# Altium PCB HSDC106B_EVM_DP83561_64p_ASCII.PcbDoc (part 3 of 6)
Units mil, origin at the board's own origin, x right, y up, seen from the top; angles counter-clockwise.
Board outline 8750.24 x 6394.7 mil, 6 copper layers (Top Layer, GND, SIG1, SIG2, GND1, Bottom Layer), stack 60.4 mil thick; 475 components, 330 nets, 1628 pads, 1086 vias.
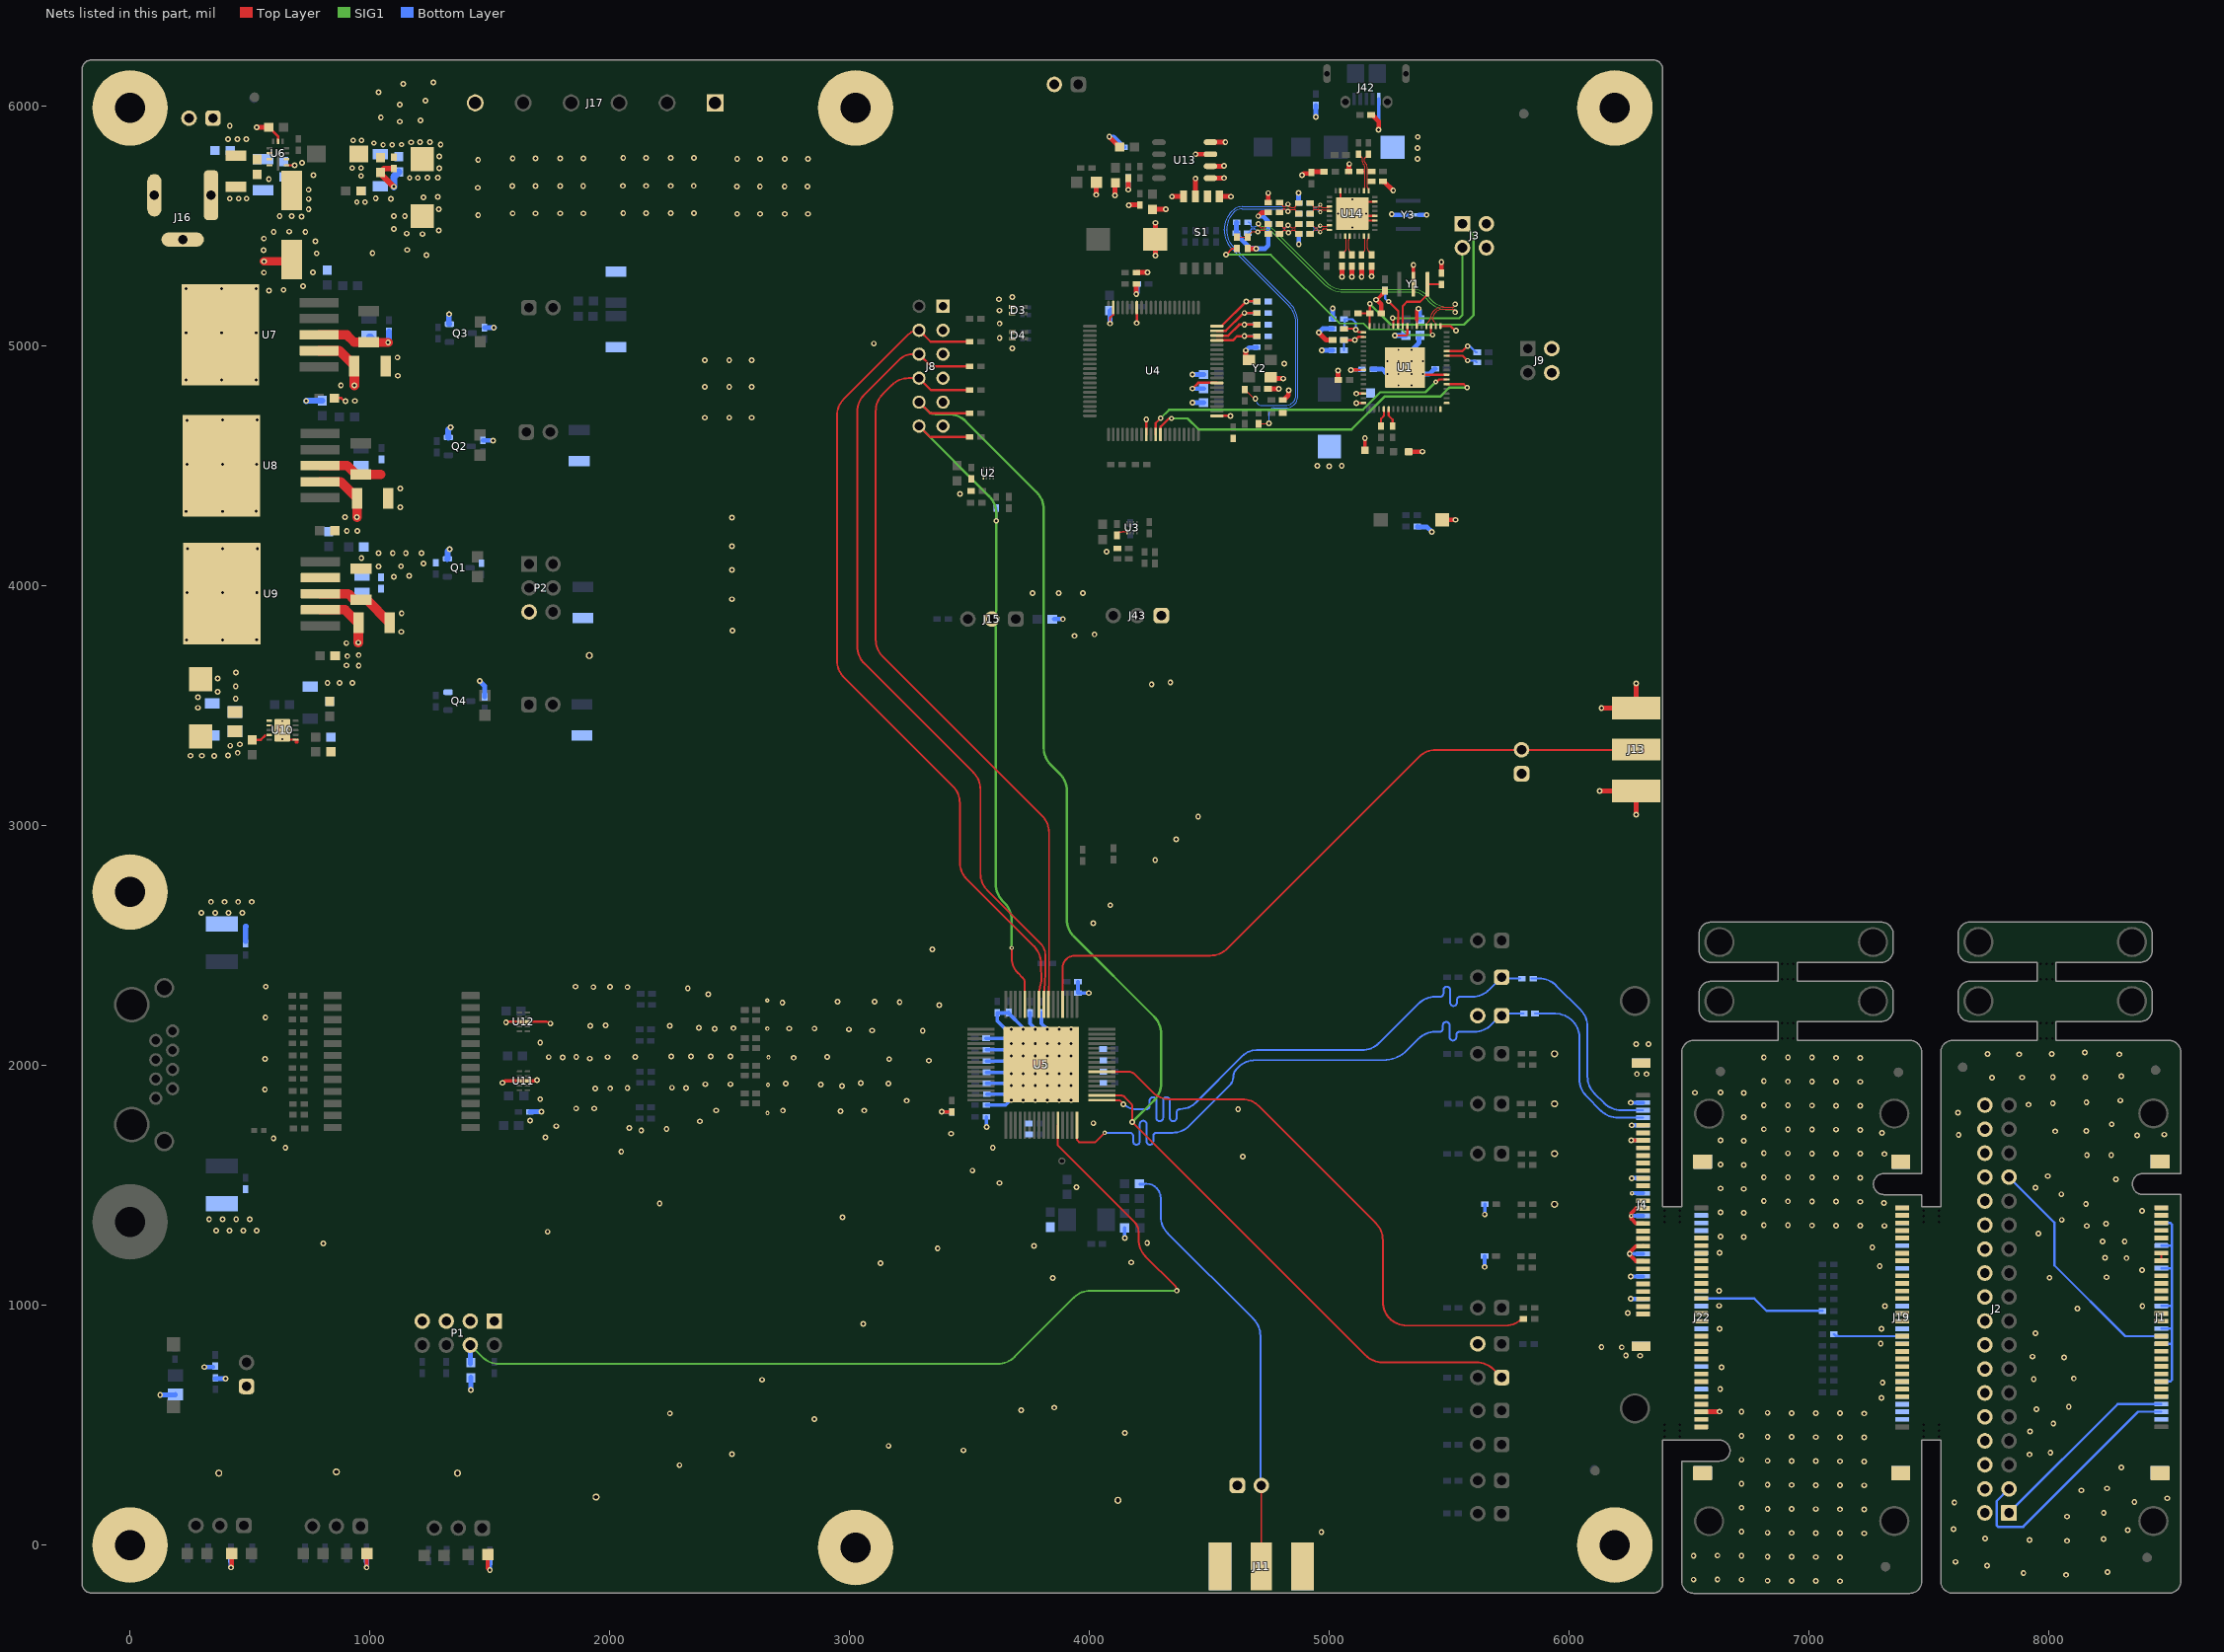
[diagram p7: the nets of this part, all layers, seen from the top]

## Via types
v1: diameter 24, hole 12, Top Layer to Bottom Layer, tented both sides, 905 vias
v2: diameter 24, hole 12, Top Layer to Bottom Layer, 63 vias
v3: diameter 18, hole 7.87, Top Layer to Bottom Layer, tented both sides, 53 vias
v4: diameter 22, hole 10, Top Layer to Bottom Layer, tented both sides, 43 vias
v5: diameter 19.68, hole 7.87, Top Layer to Bottom Layer, 21 vias
v6: diameter 22, hole 12, Top Layer to Bottom Layer, tented both sides, 1 vias

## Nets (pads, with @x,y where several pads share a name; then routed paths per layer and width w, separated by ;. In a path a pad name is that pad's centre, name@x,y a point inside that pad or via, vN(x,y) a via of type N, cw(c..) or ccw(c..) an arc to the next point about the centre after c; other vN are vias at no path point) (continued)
3V3: C80.1 C81.1 C83.1 P2.5 R100.2 R102.2 R103.2 R104.2 R105.2 R108.1 U9.4 | length 159.3
  Bottom Layer w20: v1(1458,3603.7) 1478.6,3583.1 R105.2@1478.6,3537.23 ; R103.2@1471.6,4607.23 1511.98,4607.23 v1@1513.6,4605.61 ; R104.2@1477.6,5077.23 v1@1519.22,5077.23
  other v1: 1099.81,4038.28 1163.01,4042.87 1036.21,4081.28 1129.81,4082.28 1223.01,4093.93 964.81,4116.28 1036,4136.7 1095,4136.7 1150,4136.7 1215,4136.7 1513.6,4606.61 1516.6,5077.61
5V: C50.1 C57.1 C58.2 C59.2 C60.1 C61.2 C68.1 C78.1 C85.1 C91.1 C92.2 C93.1 J17.1 J21.2 L1.2 R21.2 R22.2 R24.2 R26.2 R93.2 U7.2 U8.2 U9.2 U10.1 U10.2 U10.4 | length 925.2
  Top Layer w10: R26.2@508.6,3358.6 545.57,3358.6 562.66,3375.68 ; v1(897.6,4771.01) 893.54,4771.01 880.94,4783.61 ; R21.2@851.09,4783.61 880.94,4783.61 ; R21.2@851.09,4783.61 880.94,4783.61 ; R21.2@851.09,4783.61 880.94,4783.61
  Top Layer w40: U7.2@788.42,4980.77 872.93,4980.77 C50.1@933,4920.7 ; U8.2@792.42,4434.77 877.93,4434.77 C68.1@935,4377.7 ; U9.2@793.42,3900.77 896.93,3900.77 944,3853.7 C78.1@948,3853.7 ; v1(935.04,4836.74) C50.1@935.04,4917.7 ; v1(946.04,4286.74) C68.1@946.04,4365.7 ; v1(952.04,3763.74) C78.1@952.04,3846.7
  other v1: 350.6,3290.61 252,3292.1 299.6,3292.1 408.6,3292.61 448.42,3304.28 417.6,3333.61 457.6,3339.61 953,3667.7 902,3668.7 905.6,3707.61 953,3711.7 901.6,3761.61 903.6,4229.61 948,4229.7 896,4286.74 938,4771.7 878.97,4836.74 1239.44,5703.61 1283.6,5703.61 1289.6,5742.61 1289.6,5791.43 1294.64,5840.74 1172.13,5850.04 1209.6,5851.61 1250.6,5851.61
  other v4: 945.6,5600.61 979.6,5600.61 1165.6,5702.61 1200.21,5702.61 963.6,5709.62 925.76,5743.61 963.6,5743.61 1054.89,5839.61 1092.9,5839.61 1131.39,5840.74 1016.33,5847.02 930.06,5858.87 965.6,5858.61
5V-36V: C63.1 C64.1 C65.1 C66.1 C67.1 F1.1 U6.2 U6.9 U6.10
  other v1: 714.83,5540.45 623.6,5542.61 674.6,5542.61 744.6,5571.61 744.6,5613.61 744.6,5652.61 764.6,5712.61 716.75,5764.98 407.79,5863.96 447.23,5863.96 485.27,5863.96
5V-36V_jack: F1.2 J16.1 J18.1
AUTO_RECOVER: J8.10 J39.1 R45.1 U5.34 | length 5923.3
  Top Layer w8: U5.34@4051.41,1875.27 4130.94,1875.27 cw(c4130.94,1852.95) 4146.73,1868.74 4173.36,1842.1 cw(c4159.75,1828.49) 4179,1828.49 v1(4179,1763.7) 5151.24,791.46 ccw(c5221.96,862.17) 5221.96,762.17 5614.17,762.17 cw(c5614.17,662.17) 5684.88,732.88 J39.1@5718.99,698.77
  Top Layer w10: J8.10@3289.6,4766.61 3335.6,4720.61 R45.1@3500.98,4720.61
  SIG1 w10: J8.10@3289.6,4766.61 3326.16,4730.04 ccw(c3358.6,4762.48) 3358.6,4716.61 3412.67,4716.61 cw(c3412.67,4616.61) 3483.38,4687.32 3780.31,4390.39 cw(c3709.6,4319.68) 3809.6,4319.68 3809.6,3325.03 ccw(c3909.6,3325.03) 3838.89,3254.32 3876.31,3216.9 cw(c3805.6,3146.18) 3905.6,3146.18 3905.6,2609.03 ccw(c4005.6,2609.03) 3934.89,2538.32 4269.71,2203.49 cw(c4199,2132.78) 4299,2132.78 4299,1925.12 cw(c4199,1925.12) 4269.71,1854.41 v1(4179,1763.7)
BoardRev0: R49.1 R58.2 U4.77 | length 225.6
  Top Layer w10: U4.77@4531.24,5024.42 4598.31,5024.42 4615.69,5041.8 v1(4646.33,5041.8) R49.1@4697.98,5041.8
  Bottom Layer w10: v1(4646.33,5041.8) R58.2@4697.98,5041.8
BoardRev1: R50.1 R59.2 U4.78 | length 237.4
  Top Layer w10: U4.78@4531.24,5044.1 4578.62,5044.1 4624.59,5090.07 v1(4646.33,5090.07) R50.1@4697.98,5090.07
  Bottom Layer w10: v1(4646.33,5090.07) R59.2@4697.98,5090.07
BoardRev2: R52.1 R60.2 U4.79 | length 249.3
  Top Layer w10: U4.79@4531.24,5063.79 4567.78,5063.79 4639.65,5135.66 4643.65,5135.66 v1(4646.33,5138.34) R52.1@4697.98,5138.34
  Bottom Layer w10: v1(4646.33,5138.34) R60.2@4697.98,5138.34
BoardRev3: R53.1 R61.2 U4.80 | length 255.5
  Top Layer w10: U4.80@4531.24,5083.47 4553.38,5083.47 4554.22,5084.31 4554.22,5087.23 v1(4653.6,5186.61) R53.1@4697.98,5186.61
  Bottom Layer w10: v1(4653.6,5186.61) R61.2@4697.98,5186.61
CLKOUT: J13.1 J14.2 U5.52 | length 2920.1
  Top Layer w8: U5.52@3888.14,2255.08 3888.14,2407.15 cw(c3939.6,2407.15) 3939.6,2458.61 4504.18,2458.61 ccw(c4504.18,2558.61) 4574.89,2487.9 5374.44,3287.45 cw(c5445.15,3216.74) 5445.15,3316.74 J14.2@5801.67,3316.74 6276.29,3316.74 ccw(c6276.29,3321.41) J13.1@6279.6,3318.11
COL: J6.1 R32.1 U5.32 | length 2515.6
  Top Layer w8: U5.32@3947.2,1751.38 3947.2,1690.5 3957,1680.7 4025,1680.7 v3(4064,1719.7)
  Bottom Layer w8: v3(4064,1719.7) 4136,1719.7 4168,1719.7 cw(c4168,1705.7) 4182,1705.7 4182,1683.7 ccw(c4196,1683.7) 4210,1683.7 4210,1755.7 cw(c4224,1755.7) 4238,1755.7 4238,1683.7 ccw(c4252,1683.7) 4266,1683.7 4266,1705.7 cw(c4280,1705.7) 4280,1719.7 4318,1719.7 4346.26,1719.7 ccw(c4346.26,1819.7) 4416.97,1748.99 4585.46,1917.48 ccw(c4551.34,1951.61) 4599.6,1951.61 cw(c4647.88,1951.61) 4613.74,1985.75 4621.21,1993.22 cw(c4691.92,1922.5) 4691.92,2022.5 5226.87,2022.5 5226.93,2022.5 ccw(c5226.93,2157.06) 5322.17,2062.01 5371.55,2111.39 cw(c5442.26,2040.68) 5442.26,2140.68 5455.5,2140.68 5459.5,2140.68 ccw(c5459.5,2154.68) 5473.5,2154.68 5473.5,2167.57 cw(c5487.5,2167.57) 5501.5,2167.57 5501.5,2118.5 ccw(c5515.5,2118.5) 5529.5,2118.5 5529.5,2126.68 cw(c5543.5,2126.68) 5543.5,2140.68 5574.38,2140.68 5604.87,2140.68 ccw(c5604.87,2240.68) 5675.58,2169.97 5715.91,2210.3 cw(c5730.84,2195.37) 5730.84,2216.48 R32.1@5810.6,2216.48
COL_1: J1.54 J2.1 | length 823.2
  Bottom Layer w10: J2.1@7833.6,134.61 8286.79,587.8 J1.54@8469.11,587.8
COL_2: J22.54
COL_CS: J4.54 R32.2 | length 763.6
  Bottom Layer w8: R32.2@5857.84,2216.48 5942.6,2216.48 cw(c5942.6,2116.48) 6042.6,2116.48 6042.6,1943.35 ccw(c6142.6,1943.35) 6071.89,1872.63 6133.03,1811.49 ccw(c6203.74,1882.2) 6203.74,1782.2 J4.54@6308.86,1782.2
COL_LP: J19.54
CRS: J41.1 R33.1 U5.33 | length 2431.2
  Top Layer w8: U5.33@4051.41,1855.59 4125.41,1855.59 v1(4142,1839)
  Bottom Layer w8: v1(4142,1839) 4142,1839.7 ccw(c4194.78,1892.48) 4194.78,1817.84 4233.14,1817.84 4237.14,1817.84 ccw(c4237.14,1831.84) 4251.14,1831.84 4251.14,1853.84 cw(c4265.14,1853.84) 4279.14,1853.84 4279.14,1781.84 ccw(c4293.14,1781.84) 4307.14,1781.84 4307.14,1853.84 cw(c4321.14,1853.84) 4335.14,1853.84 4335.14,1781.84 ccw(c4349.14,1781.84) 4363.14,1781.84 4363.14,1803.84 cw(c4377.14,1803.84) 4377.14,1817.84 4377.62,1817.84 4412,1824.57 ccw(c4377.62,1908.92) 4416,1826.32 ccw(c4377.62,1908.92) 4442,1844.49 ; 4442.03,1844.52 4636.85,2039.33 cw(c4696.66,1979.52) 4696.66,2064.11 5136.5,2064.11 ccw(c5136.5,2164.11) 5207.21,2093.4 5371.58,2257.76 cw(c5442.29,2187.05) 5442.29,2287.05 5458,2287.05 5462,2287.05 ccw(c5462,2301.05) 5476,2301.05 5476,2315.17 cw(c5490,2315.17) 5504,2315.17 5504,2262.55 ccw(c5518,2262.55) 5532,2262.55 5532,2273.05 cw(c5546,2273.05) 5546,2287.05 5565,2287.05 5596.35,2287.05 ccw(c5596.35,2387.05) 5667.06,2316.34 J41.1@5718.99,2368.28 ccw(c5730.68,2379.96) 5730.68,2363.43 R33.1@5795.53,2363.43
CRS_1: J1.56 J2.3 | length 1060.9
  Bottom Layer w10: J2.3@7833.6,234.61 7782.6,183.61 7782.6,82.46 7788.46,76.61 7893.15,76.61 8372.85,556.3 J1.56@8469.11,556.3
CRS_2: J22.56
CRS_CS: J4.56 R33.2 | length 846.8
  Bottom Layer w8: R33.2@5842.77,2363.43 5874.86,2363.43 cw(c5874.86,2263.43) 5945.57,2334.14 6047.31,2232.41 cw(c5976.6,2161.7) 6076.6,2161.7 6076.6,1954.03 ccw(c6176.6,1954.03) 6105.89,1883.32 6146.21,1842.99 ccw(c6216.93,1913.7) 6216.93,1813.7 J4.56@6308.86,1813.7
CRS_LP: J19.56
D0_N: C118.1 R181.2 U14.2 | length 208.7
  Top Layer w5: R181.2@5122,5801.38 ccw(c5131.51,5801.38) 5124.78,5794.66 5130.05,5789.39 ccw(c5133.09,5792.43) 5133.09,5788.13 cw(c5133.09,5783.83) 5136.13,5786.87 cw(c5132.1,5782.84) 5137.8,5782.84 5137.8,5771.38 5137.87,5771.32 5137.87,5769.67 ccw(c5153.65,5769.67) 5142.49,5758.51 5144,5757 cw(c5130.33,5743.33) 5149.66,5743.33 5149.66,5720 ; C118.1@5127.62,5729 C118.1@5139.61,5729 ; U14.2@5144.62,5647.99 5144.62,5651.32 cw(c5153.23,5651.32) 5147.14,5657.4 ccw(c5141.06,5663.49) 5149.66,5663.49 5149.66,5720 ; 5149.66,5739.06 cw(c5139.61,5739.06) C118.1@5139.61,5729 ; C118.1@5139.61,5729 5140.66,5729 cw(c5140.66,5720) 5149.66,5720
D0_P: C119.1 R178.1 R182.2 U14.1 | length 165.4
  Top Layer w5: R182.2@5163.41,5800.88 cw(c5153.9,5800.88) 5160.62,5794.16 5155.43,5788.97 cw(c5152.21,5792.18) 5152.21,5787.63 ccw(c5152.21,5783.09) 5149,5786.3 ccw(c5152.85,5782.45) 5147.47,5783.28 ccw(c5152.85,5782.45) 5147.4,5782.45 5147.4,5775.36 5147.47,5775.29 5147.47,5769.72 ccw(c5153.75,5769.72) 5149.31,5765.27 5150.83,5763.75 cw(c5130.46,5743.38) 5159.26,5743.38 5159.26,5663.49 ccw(c5167.87,5663.49) 5161.78,5657.4 cw(c5155.7,5651.32) 5164.31,5651.32 U14.1@5164.31,5647.99
D1_N: C121.1 R184.2 U14.11 | length 160.3
  Top Layer w5: R184.2@4919.6,5596.61 cw(c4919.6,5588.77) 4925.14,5594.31 4930.46,5589 cw(c4926.33,5584.88) 4932.16,5584.88 4932.16,5584.54 ccw(c4937.16,5584.54) 4933.62,5581 ccw(c4937.16,5584.54) 4937.16,5579.53 4952.53,5579.54 ccw(c4952.53,5589.61) v3(4962.6,5589.61) ccw(c4974.22,5589.61) 4974.22,5577.99 4975,5577.99 4988.13,5577.99 ccw(c4988.13,5582.99) 4989,5578.07 cw(c4991.08,5566.3) 4991.08,5578.25 4995.92,5578.25 ccw(c4995.92,5583.25) U14.11@5000.92,5583.03
  Bottom Layer w5: C121.1@4919.6,5596.61 cw(c4919.6,5588.77) 4925.14,5594.31 4930.45,5589 cw(c4926.33,5584.88) 4932.16,5584.88 4932.16,5584.54 ccw(c4937.16,5584.54) 4933.62,5581 ccw(c4937.16,5584.54) 4937.16,5579.53 4942.21,5579.54 ccw(c4942.21,5596.73) 4954.36,5584.56 4957.15,5587.35 cw(c4962.6,5581.9) v3(4962.6,5589.61)
D1_P: C120.1 R185.2 U14.12 | length 158.2
  Top Layer w5: R185.2@4920.22,5552.61 ccw(c4920.22,5559.83) 4925.33,5554.72 4930.72,5560.12 ccw(c4926.38,5564.46) 4932.52,5564.46 4932.52,5564.94 cw(c4937.52,5564.94) 4933.99,5568.47 cw(c4937.52,5564.94) 4937.52,5569.94 4952.27,5569.94 cw(c4952.27,5559.61) v3(4962.6,5559.61) cw(c4971.38,5559.61) 4971.38,5568.39 4988.13,5568.39 cw(c4988.13,5563.39) 4988.97,5568.32 ccw(c4991.08,5580.08) 4991.08,5568.13 4995.92,5568.13 cw(c4995.92,5563.13) U14.12@5000.92,5563.37
  Bottom Layer w5: C120.1@4920.22,5552.61 ccw(c4920.22,5559.83) 4925.33,5554.72 4930.72,5560.12 ccw(c4926.38,5564.46) 4932.52,5564.46 4932.52,5564.94 cw(c4937.52,5564.94) 4933.99,5568.47 cw(c4937.52,5564.94) 4937.52,5569.94 4942.29,5569.94 cw(c4942.29,5552.3) 4954.76,5564.77 4958.03,5561.5 ccw(c4962.6,5566.07) v3(4962.6,5559.61)
D2_N: C125.1 R192.2 U14.15 | length 134.9
  Top Layer w5: R192.2@4920.03,5509.5 cw(c4920.03,5500) 4926.75,5506.72 4933.72,5499.75 ccw(c4947.36,5513.39) 4947.36,5494.1 ccw(c4947.36,5505.72) 4955.57,5497.5 4960.02,5501.95 cw(c4961.6,5500.37) v3(4961.6,5502.61) ; v3@4962.26,5502.61 ccw(c4970.37,5510.71) 4968.81,5499.36 ccw(c4970.37,5510.71) 4970.37,5499.25 4985.42,5499.25 ccw(c4985.42,5507.86) 4991.51,5501.77 cw(c4997.6,5495.68) 4997.6,5504.29 U14.15@5000.92,5504.29
  Bottom Layer w5: C125.1@4920.03,5509.5 cw(c4920.03,5500) 4926.75,5506.72 4932.06,5501.41 cw(c4929.1,5498.46) 4933.28,5498.46 ccw(c4937.46,5498.46) 4934.5,5495.51 ccw(c4938.62,5499.63) 4938.62,5493.8 4941.64,5493.8 4946.91,5493.8 ccw(c4946.91,5506.51) 4951.02,5494.49 ccw(c4946.91,5506.51) v3@4955.89,5497.53
D2_P: C124.1 R193.2 U14.16 | length 142.1
  Top Layer w5: R193.2@4920.03,5468.5 ccw(c4920.03,5478.01) 4926.75,5471.29 4934.74,5479.28 cw(c4947.36,5466.66) 4944.11,5484.2 cw(c4947.36,5466.66) 4947.36,5484.5 cw(c4947.36,5472.64) 4955.75,5481.03 4959.91,5476.87 ccw(c4962,5478.95) v3(4962,5476) 4972.7,5486.7 cw(c4975.99,5482.93) 4973.04,5486.97 ccw(c4961.6,5502.61) 4974.7,5488.33 cw(c4978.08,5484.65) 4978.11,5489.65 4985.42,5489.65 cw(c4985.42,5481.04) 4991.51,5487.13 ccw(c4997.6,5493.21) 4997.6,5484.61 U14.16@5000.92,5484.61
  Bottom Layer w5: C124.1@4920.03,5468.5 ccw(c4920.03,5478.01) 4926.75,5471.29 4932.06,5476.59 ccw(c4929.1,5479.55) 4933.28,5479.55 cw(c4937.46,5479.55) 4934.5,5482.5 cw(c4938.62,5478.38) 4938.62,5484.2 4945.62,5484.2 4949.1,5484.2 cw(c4949.1,5475.82) 4949.2,5484.2 cw(c4949.1,5475.82) 4950.44,5484.1 cw(c4949.1,5475.82) 4955.03,5481.75 ; v3@4960.02,5474.52 v3@4963,5474.52
DM3: R188.2 U14.19 | length 86.2
  Top Layer w5: R188.2@5053.44,5380.94 5053.44,5384.88 5067.97,5399.41 ; U14.19@5065.88,5459.02 5065.88,5455.69 ccw(c5074.49,5455.69) 5068.4,5449.61 cw(c5062.32,5443.52) 5070.92,5443.52 5070.92,5406.53 cw(c5060.85,5406.53) 5067.98,5399.42
DM4: R190.2 U14.23 | length 84.3
  Top Layer w5: R190.2@5134.6,5381.23 cw(c5144.1,5381.23) 5137.38,5387.95 R190.2@5143.91,5394.48 ; R190.2@5143.94,5394.48 5144.98,5395.52 ccw(c5133.68,5406.82) 5149.66,5406.82 5149.66,5443.52 ccw(c5141.06,5443.52) 5147.14,5449.61 cw(c5153.23,5455.69) 5144.62,5455.69 U14.23@5144.62,5459.02
DP3: R189.2 U14.20 | length 76.5
  Top Layer w5: U14.20@5085.57,5459.02 5085.57,5455.69 cw(c5076.96,5455.69) 5083.04,5449.61 ccw(c5089.13,5443.52) 5080.52,5443.52 5080.52,5406.53 ccw(c5106.92,5406.53) R189.2@5088.24,5387.88 ; R189.2@5088.25,5387.86 R189.2@5089.63,5386.48
DP4: R191.2 U14.24 | length 86.5
  Top Layer w5: U14.24@5164.31,5459.02 5164.31,5455.69 cw(c5155.7,5455.69) 5161.78,5449.61 ccw(c5167.87,5443.52) 5159.26,5443.52 5159.26,5406.82 ccw(c5175.24,5406.82) 5163.94,5395.52 5164.11,5395.36 ccw(c5166.23,5397.48) 5166.23,5394.48 cw(c5166.23,5391.47) 5168.35,5393.6 5174,5387.95 cw(c5167.28,5381.23) R191.2@5176.79,5381.23
EXT_REF_CLK: J11.1 J12.2 R84.1 | length 1840.8
  Top Layer w8: J11.1@4716.6,-89.39 J12.2@4716.6,248.61
  Bottom Layer w8: R84.1@4209.09,1506.61 4228.06,1506.61 4237.58,1506.61 cw(c4237.58,1447.28) 4296.91,1447.28 4296.91,1371.36 ccw(c4396.91,1371.36) 4326.19,1300.65 4683.31,943.53 cw(c4612.6,872.82) 4712.6,872.82 J12.2@4712.6,248.61 ; R84.1@4209.22,1503.23 R84.1@4228.06,1503.23
EZFET_AVBUS: C2.1 R3.1 R5.2 U1.1 | length 206.9
  Top Layer w9: R3.1@5066.24,5073.7 5107,5073.7 5110,5070.7 v1(5110,5068.7) 5110,5066.7 5114,5066.7 5122.37,5058.33 U1.1@5142.77,5058.33
  Bottom Layer w9: R5.2@5064.24,5072.61 5064.24,5112.7 5096.05,5112.7 5110,5098.75 v1(5110,5068.7)
EZFET_AVCOUT2ADC: C3.1 R4.1 R6.2 U1.2 | length 175.4
  Top Layer w10: C3.1@5061.22,5025.7 5061.27,5025.65 5106.55,5025.65 v1(5106.6,5025.61) 5108.5,5025.61 5121.54,5038.65 U1.2@5142.77,5038.65
  Bottom Layer w10: R6.2@5061.22,4982.7 R4.1@5061.22,5025.7 5061.27,5025.65 5106.55,5025.65 v1(5106.6,5025.61)
EZFET_LED0: R1.2 U1.20 | length 75.5
  Top Layer w9: R1.2@5216,4668.67 5216,4697.67 5227.39,4709.06 U1.20@5227.39,4739.43
EZFET_LED1: R2.2 U1.21 | length 77.8
  Top Layer w9: U1.21@5247.1,4737.47 5247.08,4710.62 5264,4693.7 R2.2@5264,4666.7
EZFET_PUD_N: C128.1 R196.1 U1.52 | length 1245
  Top Layer w5: v4@4704.61,5509.56 ccw(c4720.37,5509.56) 4720.35,5493.8 4726.79,5493.8 ccw(c4726.79,5499.63) 4730.91,5495.51 ccw(c4727.95,5498.46) 4732.13,5498.46 cw(c4736.31,5498.46) 4733.35,5501.42 4738.66,5506.72 cw(c4745.38,5500) R196.1@4745.38,5509.5 ; U1.52@5404.58,5083.92 cw(c5429.34,5083.92) 5411.83,5101.43 5415.67,5105.27 ; 5415.68,5105.28 ccw(c5404.95,5115.98) 5416.46,5106.12 ccw(c5404.95,5115.98) 5420.11,5115.98 cw(c5473.7,5109.29) 5473.7,5163.3 5513.3,5163.3 ccw(c5513.3,5175) v1(5525,5175)
  SIG1 w5: v4(4703.6,5510.61) 4703.6,5510.11 ccw(c4730.03,5536.54) 4730.03,5499.16 4732.55,5499.16 cw(c4732.55,5446.07) 4770.09,5483.61 4987.41,5266.29 ccw(c5058.12,5337) 5058.12,5237 5348.03,5237 cw(c5348.03,5155.73) 5405.5,5213.2 5426.41,5192.29 ccw(c5497.12,5263) 5496.98,5163 ccw(c5497.12,5263) 5497.12,5163 5513,5163 ccw(c5513,5175) v1(5525,5175)
  Bottom Layer w5: C128.1@4665.22,5515.06 ccw(c4661.24,5511.07) C128.1@4661.24,5516.7 cw(c4661.24,5505.06) 4672.89,5505.06 4672.89,5503.71 ccw(c4677.89,5503.71) 4674.35,5500.18 ccw(c4677.89,5503.71) 4677.89,5498.71 4685.62,5498.71 ccw(c4685.62,5519.15) 4700.06,5504.69 v4@4701.92,5506.55
EZFET_PUD_P: C127.1 R197.1 R199.1 R200.2 U1.50 | length 1317.4
  Top Layer w5: R197.1@4614.59,5454.39 R200.2@4659.87,5454.39 4659.87,5458.33 4673.27,5471.73 ; 4673.28,5471.75 cw(c4685.03,5459.97) 4685.03,5476.61 v4(4702.6,5476.61) ; v4@4703.6,5484.2 4721,5484.2 4726.79,5484.2 cw(c4726.79,5478.38) 4730.91,5482.5 cw(c4727.95,5479.55) 4732.13,5479.55 ccw(c4736.31,5479.55) 4733.35,5476.6 4738.66,5471.29 ccw(c4745.38,5478.01) R199.1@4745.38,5468.5 ; U1.50@5443.95,5083.92 ccw(c5414.66,5083.92) 5435.37,5104.63 cw(c5447.12,5116.38) 5430.5,5116.38 5430.5,5116.61 cw(c5473.7,5110) 5473.7,5153.7 5513.3,5153.7 cw(c5513.3,5142) v1(5525,5142)
  SIG1 w5: v4(4702.6,5476.61) 4703.1,5476.61 cw(c4730.74,5448.96) 4730.74,5488.06 4732.5,5488.06 cw(c4732.5,5445.94) 4762.28,5475.72 4979.59,5258.41 ccw(c5058.08,5336.9) 5058.08,5225.9 5348,5225.9 cw(c5348,5155.65) 5397.68,5205.32 5421.12,5181.88 ccw(c5493.5,5254.26) 5493.5,5151.9 5515.1,5151.9 cw(c5515.1,5142) v1(5525,5142)
  Bottom Layer w5: C127.1@4659.87,5471.7 ccw(c4659.87,5478.71) 4664.82,5473.75 4670.25,5479.18 ccw(c4665.84,5483.6) 4672.08,5483.6 4672.08,5484.11 cw(c4677.08,5484.11) 4673.55,5487.65 cw(c4677.08,5484.11) 4677.08,5489.11 4685.35,5489.11 cw(c4685.35,5477.67) 4689.09,5488.49 cw(c4685.35,5477.67) 4693.43,5485.77 v4(4702.6,5476.61)
EZFET_PUR: R197.2 U1.51 | length 1096.6
  Top Layer w8: v1(4569.63,5381.56) 4595.22,5407.15 R197.2@4614.59,5407.15 ; U1.51@5424.26,5085.01 5424.26,5053.5 v4(5430.97,5046.79)
  SIG1 w8: v1(4569.63,5381.56) 4756.44,5381.56 5043.21,5094.79 5142.01,5094.79 5166.64,5070.17 5303.83,5070.17 5327.21,5046.79 v4(5430.97,5046.79)
EZFET_RST: C8.1 J3.1 R8.1 U1.64 | length 1028.5
  Top Layer w9: R8.1@5119.62,5136.7 C8.1@5169.38,5136.7 5168.32,5135.64 U1.64@5168.32,5083.92
  Top Layer w10: C8.1@5169.38,5136.7 v4(5169.38,5176.7)
  SIG1 w10: v4(5169.38,5176.7) 5256.38,5089.7 5561.69,5089.7 5602,5130.01 5602,5463.7 J3.1@5555,5510.7
EZFET_SBW_RST: R10.1 U1.43 | length 136.4
  Top Layer w9: U1.43@5489.22,4959.91 5555.79,4959.91 v4(5576,4939.7)
  Bottom Layer w9: v4(5576,4939.7) 5607.38,4939.7 R10.1@5614.38,4932.7
EZFET_SBW_TST: R9.1 U1.44 | length 144.6
  Top Layer w9: U1.44@5489.22,4979.59 5555.02,4979.59 v4(5576,5000.57)
  Bottom Layer w9: v4(5576,5000.57) 5586.13,5000.57 5612,4974.7 R9.1@5614.38,4974.7
EZFET_TEST: J3.3 U1.59 | length 609.4
  Top Layer w9: v4(5264.6,5117.61) 5266.56,5115.65 5266.56,5084.15 U1.59@5266.78,5083.92 U1.59@5266.77,5079.86
  SIG1 w9: v4@5266.6,5116.61 5541.8,5116.61 5555,5129.81 J3.3@5555,5406.64
EZFET_UARTCTS: U1.32
EZFET_UARTRTS: U1.33
EZFET_UARTRXD: U1.38 U4.51 | length 1335.9
  Top Layer w9: v4(5443.94,4851.02) 5447.46,4851.02 5458.05,4861.61 5489.1,4861.61 U1.38@5489.22,4861.48
  Top Layer w10: U4.51@4276.31,4631.7 4276.31,4679.02 v4(4297,4699.7)
  SIG1 w10: v4(4297,4699.7) 4332,4734.7 5139.69,4734.7 5212.69,4807.7 5400.63,4807.7 v4(5443.94,4851.02)
EZFET_UARTTXD: U1.37 U4.52 | length 1505.2
  Top Layer w9: U1.37@5489.22,4841.8 5559.9,4841.8 v4(5574,4827.7)
  Top Layer w10: U4.52@4296,4631.7 4296.91,4632.61 4296.91,4664.15 4331.45,4698.7 v4@4340.76,4698.7
  SIG1 w10: v4(4342,4698.7) 4409.39,4698.7 4455.48,4652.61 5092.73,4652.61 5229.95,4789.83 5462.63,4789.83 5500.5,4827.7 v4(5574,4827.7)
EZFET_VREF: C1.1 U1.9 | length 100.2
  Top Layer w9: 5116.15,4900.85 U1.9@5142.77,4900.85
  Top Layer w15: v1(5089.85,4900.85) 5116.15,4900.85
  Bottom Layer w15: v1(5089.85,4900.85) 5133.22,4900.85 C1.1@5135.98,4903.61
EZFET_VUSB: C9.1 U1.54 | length 126.8
  Top Layer w9: U1.54@5365.21,5083.92 5365.21,5109.48
  Top Layer w15: 5365.21,5109.48 5365.21,5150.21 v1(5371.6,5156.61)
  Bottom Layer w15: v1(5371.6,5156.61) 5378.99,5149.22 C9.1@5378.99,5108.2
EZFET_XIN: C5.1 U1.57 Y1.3 | length 308.3
  Top Layer w9: U1.57@5306.15,5083.92 5306.15,5167.33 5323.94,5185.11 5378.64,5185.11 5405.46,5211.93 5406.28,5211.93 5409.65,5215.3 Y1.3@5409.65,5258.61 5466.98,5258.61 C5.1@5467.6,5257.98
EZFET_XOUT: R7.1 U1.58 | length 165.7
  Top Layer w9: v4(5247,5186.52) 5287.97,5145.55 5287.97,5107.92 5286.46,5106.41 U1.58@5286.47,5083.92
  Bottom Layer w9: R7.1@5233,5224.9 5233,5198.29 5244.77,5186.52 v4(5247,5186.52)
GND: C1.2 C2.2 C3.2 C4.2 C5.2 C6.2 C7.2 C8.2 C9.2 C10.2 C11.2 C12.2 C13.2 C14.2 C15.2 C16.2 C17.2 C18.2 C19.1 C20.2 C21.2 C22.2 C23.2 C24.2 C25.2 C26.2 C27.2 C28.2 C29.2 C30.2 C31.2 C32.2 C33.2 C34.2 C35.2 C36.2 C37.2 C38.2 C39.2 C40.2 C41.2 C42.2 C43.2 C44.2 C45.2 C46.2 C47.2 C48.2 C49.2 C50.2 C51.1 C52.2 C53.2 C55.2 C57.2 C58.1 C59.1 C60.2 C61.1 C62.2 C63.2 C64.2 C65.2 C66.2 C67.2 C68.2 C70.2 C71.2 C73.2 C74.1 C75.1 C76.1 C77.1 C78.2 C80.2 C81.2 C83.2 C84.1 C85.2 C86.2 C87.2 C88.1 C91.2 C92.1 C93.2 C94.2 C108.1 C109.1 C110.2 C111.2 C112.2 C113.2 C114.2 C115.2 C116.2 C117.1 C118.2 C119.2 C120.2 C121.2 C122.2 C123.2 C124.2 C125.2 C126.2 C127.2 C128.2 C129.2 D1.1 D2.1 D3.3 D3.4 D4.3 D4.4 J3.2 J3.4 J4.1 J4.3 J4.5 J4.6 J4.7 J4.9 J4.12 J4.13 J4.15 J4.18 J4.19 J4.21 J4.23 J4.25 J4.28 J4.29 J4.31 J4.34 J4.35 J4.37 J4.38 J4.39 J4.41 J4.43 J4.45 J4.47 J4.48 J4.49 J4.51 J4.52 J4.58 J4.MP1 J4.MP2 J4.MP3 J4.MP4 J5.2 J6.2 J8.1 J8.3 J8.5 J8.7 J8.9 J8.11 J9.2 J9.4 J10.1 J11.2 J11.3 J11.4 J11.5 J12.1 J13.2 J13.3 J13.4 J13.5 J14.1 J16.2 J16.3 J17.6 J18.2 J42.5 J43.1 LD2.2 LD4.2 LD6.2 LD7.2 M1.1 M2.1 M3.1 M4.1 M5.1 M6.1 M7.1 P1.1 P1.3 P1.5 P1.7 Q1.2 Q2.2 Q3.2 Q4.2 R5.1 R6.1 R30.1 R35.1 R37.1 R58.1 R59.1 R60.1 R61.1 R74.2 R79.2 R83.2 R90.1 R91.1 R94.1 R95.1 R98.1 R101.1 R126.1 R145.2 R146.2 R150.1 R154.1 R158.1 R162.1 R171.1 R176.1 R177.2 R186.1 R187.1 R188.1 R189.1 R190.1 R191.1 R194.1 R195.1 R200.1 S1.5 S1.6 S1.7 S1.8 S2.1 TP1.1 TP2.1 TP3.1 TP4.1 TP5.1 TP6.1 TP7.1 TP8.1 TP9.1 TP10.1 U1.14 U1.16 U1.39 U1.49 U1.56 U1.65 U2.1 U3.1 U4.14 U4.19 U4.49 U4.61 U4.68 U5.65 U6.1 U6.6 U6.11 U7.3 U7.6 U8.3 U8.6 U9.3 U9.6 U10.6 U10.11 U11.3@1624.13,1936.31 U11.8@1657,1936.31 U12.3@1624.13,2182.31 U12.8@1657,2182.31 U13.5 U13.6 U13.7 U13.8 U14.7 U14.27 U14.28 U14.31 U14.33 Y1.2 Y2.2 Y2.4 Y3.2 | length 10894.2
  Top Layer w6: C14.2@4114.6,4210.98 4114.6,4214.92 4123.41,4223.73 4134.18,4223.73 4137.3,4226.86 U3.1@4155.93,4226.86
  Top Layer w9: U10.11@635,3398.7 635,3388.7 664,3359.7 689.75,3359.7 U10.6@690.12,3359.33 690.12,3347.58 691.58,3346.12 699.02,3346.12 ; 699,3346.14 U10.6@699,3358.7 ; U14.7@5046.2,5647.99 5046.2,5602.72 v5(5095.41,5553.5) ; v1(5112.36,4763.06) U1.16@5142.77,4763.06 ; v1(5113.27,4802.43) U1.14@5142.77,4802.43 ; U14.27@5189.9,5523.98 5124.94,5523.98 U14.33@5105.25,5543.66 ; U14.28@5189.9,5543.66 U14.33@5105.25,5543.66 ; U14.31@5189.9,5602.72 5144.62,5602.72 v5(5095.41,5553.5) ; v1(5273.51,5044.52) 5320.56,5044.52 5325.84,5049.8 U1.56@5325.84,5083.92 ; U1.65@5315.99,4910.69 5345.52,4881.17 U1.39@5489.22,4881.17 ; U1.49@5463.63,5083.92 5505.74,5083.92 5524.96,5064.7 v1(5527.96,5064.7) ; v5(5095.41,5553.5) U14.33@5105.25,5543.66
  Top Layer w10: C62.2@577.61,5913.61 578.59,5913.61 616.52,5875.68 616.52,5853.8 U6.6@616.6,5853.72 ; U6.1@652.03,5754.31 652.11,5754.39 685.39,5754.39 v1(685.6,5754.61) ; v1(1567.72,2180.31) cw(c1572.57,2175.46) 1572.57,2182.32 U12.3@1624.13,2182.31 U12.8@1657,2182.31 1735.34,2182.31 cw(c1735.34,2157.34) v1(1753,2175) ; v1(4085.85,5094.61) 4085.85,5118.41 4099.15,5131.72 U4.19@4099.15,5161.23 U4.19@4098.24,5160.32 ; U4.14@4197.57,5161.23 v1(4197.6,5096.61) ; U4.49@4236.94,4631.7 v1(4236.94,4695.24) ; v1(4429.46,4823.24) 4453.47,4847.25 U4.68@4531.24,4847.25
  Top Layer w11: U4.61@4531.24,4709.46 v1(4587.79,4709.46)
  Top Layer w15: v1(1552,1927.68) cw(c1572.83,1906.85) 1572.83,1936.32 U11.3@1624.13,1936.31 U11.8@1657,1936.31 1696.23,1936.31 v1(1696.23,1938.66) ; v1(3383.6,1807.95) 3385.57,1805.98 C51.1@3426.41,1805.98 ; D1.1@5148.79,4565.7 v1(5148.79,4616.8) ; v1@5197.57,5193.46 5232.1,5227.99 C4.2@5232.1,5231.93 ; Y1.2@5350.6,5258.61 v1(5350.6,5338.61)
  Top Layer w17: v1(420.5,-93.25) 423.66,-90.09 LD6.2@423.66,-35 ; v1(986,-93.25) 986.84,-92.41 LD4.2@986.84,-35 ; LD2.2@1491.34,-40 1491.34,-96.19 v1(1500,-104.85) ; v3(6258.23,1372.76) 6258.42,1372.56 6258.42,1362.21 6278.03,1342.6 6307.52,1342.6 J4.25@6308.86,1341.26 ; 6258.42,1383.31 6278.03,1402.91 6307.52,1402.91 J4.29@6308.86,1404.25 ; v1(6258.65,1688.01) J4.47@6306.56,1688.01 ; J4.15@6308.86,1183.78 6307.52,1185.12 6278.03,1185.12 6253.27,1209.88 6253.27,1213.94 v1(6251.93,1215.28) 6253.27,1216.62 6253.27,1220.67 6278.03,1245.43 6307.52,1245.43 J4.19@6308.86,1246.77
  Top Layer w20: v1(527.6,5912.61) 528.1,5913.11 577.11,5913.11 C62.2@577.61,5913.61 ; v1(4028.2,5631.61) 4028.57,5631.98 4028.57,5682.33 LD7.2@4028.94,5682.7 ; v1(4082.6,5873.61) 4082.6,5872.62 4124.52,5830.7 C111.2@4125.5,5830.7 ; v1(4106.6,5628.61) 4107.1,5629.11 4107.1,5680.61 C114.2@4107.6,5681.11 ; v1(4161.6,5652.62) C112.2@4161.6,5700.64 ; v1(4164.5,5587.94) 4165.58,5587.94 4166.96,5589.31 R176.1@4210,5589.31 ; C23.2@4195.41,5259.61 4195.5,5259.51 4195.5,5217.7 v1(4195.6,5217.61) ; C22.2@4195.41,5306.61 4195.91,5307.11 4241.1,5307.11 v1(4241.6,5307.61) ; C115.2@4263.6,5570.61 v1(4318.41,5570.61) v1@4320.92,5568.11 ; v1(4274.69,5378.31) C21.2@4274.69,5445.61 v1(4274.69,5514.69) ; v1(4344.17,5623.72) 4344.66,5624.21 4391.51,5624.21 S1.8@4392,5624.7 ; S1.7@4442,5624.7 4442.3,5625 4442.3,5699.31 v1(4442.6,5699.61) ; v1(4442.6,5800.61) 4442.65,5800.65 4504.24,5800.65 U13.7@4504.28,5800.7 ; U13.5@4504.28,5700.7 4504.74,5701.15 4561.15,5701.15 v1(4561.6,5701.61) ; U13.6@4504.28,5750.7 4557.61,5750.7 4559.52,5752.61 v1(4560.6,5752.61) ; U13.8@4504.28,5850.7 4504.74,5851.15 4566.15,5851.15 v1(4566.6,5851.61) ; S1.5@4542,5624.7 4542.49,5624.21 4589.74,5624.21 v1(4590.23,5623.72) ; v1(4652.27,4981.94) 4652.27,4953.69 4663.92,4942.04 Y2.2@4665.32,4942.04 ; R200.1@4659.87,5407.15 v1(4694.87,5407.15) ; v6(4704,5542.7) 4718.8,5557.5 R186.1@4745.38,5557.5 ; C15.2@4744.6,4822.61 v1(4789.6,4822.61) ; R187.1@4745.38,5598.72 v1(4745.38,5638.38) ; Y2.4@4755.87,4871.17 4761.68,4865.37 4807.83,4865.37 v1(4808.6,4864.61) ; C123.2@4806.22,4775.61 4810.16,4775.61 4829.83,4795.28 4829.83,4814.98 v1(4830.6,4815.74) ; v1(4886,5713) 4887.08,5713 4894.47,5720.39 4923.19,5720.39 4925,5722.2 C129.2@4925,5724.32 ; C129.2@4925,5727.7 C126.2@4977.38,5727.7 ; v1(4956.03,5056.7) 4987.03,5025.7 C3.2@5017.03,5025.7 ; C11.2@5036.38,4859.7 v1(5036.38,4898.08) ; R188.1@5053.44,5335.66 5053.6,5335.51 v1(5053.6,5289.61) ; C118.2@5082.35,5727.49 5082.35,5759.13 v1(5083,5759.79) ; v1(5094.25,5289.75) R189.1@5094.25,5333.98 ; v1(5134.6,5289.4) R190.1@5134.6,5333.98 ; v1(5176.79,5290.9) 5176.22,5291.47 5176.22,5310.86 5176.41,5311.05 5176.41,5333.61 R191.1@5176.79,5333.98 ; C117.1@5180.41,5962.69 5206.02,5937.09 5206.02,5904.62 5205.18,5903.78 v1(5205.18,5902.7) ; v1@5197.57,5193.46 5216.62,5174.41 C8.2@5216.62,5136.7 ; C119.2@5223.62,5687 5227.56,5687 5264.89,5649.67 v1(5266.22,5649.67) ; D2.1@5331.18,4560.04 v1(5388.26,4560.04) ; C5.2@5467.6,5305.23 v1(5467.6,5351.6) ; S2.1@5470.95,4275.7 v1(5526,4275.7) ; v1(6127.61,3145.61) J13.3@6279.6,3145.61 v1(6279.6,3045.6) ; v1(6134.61,3490.61) J13.2@6279.6,3490.61 v1(6279.6,3593.4)
  Top Layer w23: C61.1@1058.87,5740.37 C59.1@1098.85,5740.37
  Top Layer w25: C61.1@1043.6,5724.11 1049.8,5717.91 1049.8,5714.73 v1(1099.47,5665.06) ; C61.1@1043.6,5725.09 C61.1@1058.87,5740.37
  Top Layer w35: v1@558.68,5353.61 666.3,5353.61 C63.2@674.6,5361.91
  Top Layer w38: U7.3@788.42,5047.7 904,5047.7 905,5046.7 ; 904,5046.7 934,5016.7 C52.2@977,5016.7 ; C52.2@995,5015.74 v1(1076.04,5015.74)
  Top Layer w40: U8.3@792.42,4501.7 906,4501.7 C70.2@942,4465.7 ; U9.3@793.42,3967.7 910,3967.7 C80.2@934,3943.7 ; C70.2@962,4464.74 1045.04,4464.74 ; C80.2@963,3942.74 985.92,3942.74 C78.2@1081.96,3846.7
  Bottom Layer w10: v1@4693.02,5408.99 v1(4694.87,5407.15)
  Bottom Layer w15: v1(3383.6,1807.95) 3384.58,1806.97 3425.43,1806.97 R83.2@3426.41,1805.98 ; C33.2@3569.22,2113.61 3648.66,2113.61 3671.56,2090.7 3671.56,2088.26 3648.91,2065.61 C26.2@3570.22,2065.61 ; v1(3570.87,1743.87) C38.2@3570.87,1786.1 ; C39.2@3570.87,1834.92 3650.78,1834.92 3671.56,1855.7 v2(3674,1855.7) 3649.09,1880.61 C35.2@3572.22,1880.61 ; C27.2@3571.22,1971.61 3665.66,1971.61 3671.56,1965.7 v2(3674,1965.7) ; C28.2@3571.22,2018.61 3649.47,2018.61 3671.56,2040.7 v2(3674,2040.7) ; C34.2@3571.41,1925.61 3661.66,1925.61 3671.56,1915.7 v2(3674,1915.7) ; C37.2@3663.6,2220.98 C37.2@3663.6,2219.08 ; v2(3674,2150.7) 3672.28,2152.42 3649.14,2152.42 3615.74,2185.82 3615.74,2219.08 C37.2@3663.6,2219.08 ; v2(3724,2150.7) 3722.28,2152.42 3722.28,2158.37 3663.6,2217.05 C37.2@3663.6,2219.08 ; C44.2@3752.6,2218.98 3752.6,2174.54 3774,2153.14 v2(3774,2150.7) ; C45.2@3799.6,2218.98 3799.6,2175.1 v2(3824,2150.7) ; C31.2@3952.04,2349.36 C32.2@3952.04,2302.41 v1(3997.8,2302.41) ; C49.2@4146.98,1322.8 4146.98,1280.83 v1(4147.46,1280.34) ; v1@5204,5902.7 v1(5205.18,5902.7) 5206.02,5903.54 J42.5@5206.02,6031.3 ; v1(5647.85,1159.98) R154.1@5647.85,1205.42 ; v1(5648.39,1378.61) R158.1@5648.39,1421.22
  Bottom Layer w17: v1(6251.93,1215.28) J4.18@6308.86,1215.28 ; v1(6256.2,1845.2) J4.58@6308.86,1845.2 J4.58@6308.96,1845.1 ; v1(6256.49,1026.93) 6257.12,1026.3 J4.6@6308.86,1026.3 ; v1@6256.57,1121.41 v1(6257.2,1120.79) J4.12@6308.86,1120.79 ; v3(6258.23,1372.76) J4.28@6308.86,1372.76 ; v1(6258.65,1688.01) 6258.79,1687.86 6308.71,1687.86 J4.48@6308.86,1687.72 ; v1(6260.29,1750.71) J4.52@6308.86,1750.71 ; v3(6262,1467.24) J4.34@6308.86,1467.24
  Bottom Layer w18: v1@6260.44,1530.24 J4.38@6308.86,1530.24
  Bottom Layer w20: v1(125.6,626.61) 188.09,626.61 C47.2@189.29,627.8 ; v1(309.67,742.6) C46.2@345.9,742.6 ; R79.2@355.45,694.45 v1(397.5,694.45) ; v1(420.5,-93.25) R171.1@420.5,-57.02 ; v1(986,-93.25) R162.1@986,-57.02 ; v1(1420.6,646.61) R91.1@1420.6,698.11 R91.1@1420.6,701.32 ; v1(1500,-104.85) R150.1@1500,-68.62 ; R126.1@1666.62,1806 1667.62,1807 v1(1715,1807) ; R90.1@3852.93,3861.93 v1(3889.15,3861.93) ; v1(4082.6,5873.61) 4083.36,5872.84 4100.74,5872.84 4138.23,5835.35 4138.23,5831.42 4140.04,5829.61 C110.2@4143.98,5829.61 ; v1(4085.85,5094.61) 4085.85,5148.17 C18.2@4090.38,5152.7 ; v1(4161.6,5652.62) C113.2@4161.6,5700.64 ; v1(4195.6,5217.61) 4195.6,5218.69 4199.38,5222.47 C24.2@4199.38,5259.61 ; v1(4429.46,4764.18) C19.1@4476.46,4764.18 ; v1(4429.46,4823.24) C20.2@4475.77,4823.24 C20.2@4476.46,4823.24 ; v1(4429.79,4881.61) C17.2@4476.79,4881.61 ; C128.2@4614,5516.7 4613.31,5516.01 4613.31,5472.39 C127.2@4612.62,5471.7 4616.56,5471.7 4618.37,5469.89 4618.37,5460.36 4669.74,5408.99 v1@4693.02,5408.99 ; v1(4652.27,4981.94) 4653.35,4981.94 4665.21,4993.8 4696.17,4993.8 C16.2@4697.98,4995.61 ; v1(4694.87,5407.15) 4732.14,5407.15 4745.38,5420.39 4745.38,5519.83 4722.5,5542.7 v6(4704,5542.7) ; C121.2@4872.35,5596.61 v1(4872.35,5639.65) ; v1(4872.79,5425) C124.2@4872.79,5468.5 ; v1(4944,5955.9) R177.2@4944,6004.08 ; v1(4956.03,5056.7) 4971.94,5072.61 R5.1@5013.98,5072.61 ; v1(4968,4982.7) R6.1@5013.98,4982.7 ; C2.2@5013.98,5113.61 5014.33,5113.96 5014.33,5156.74 v1(5014.68,5157.09) ; C1.2@5178.24,4904.7 5220.81,4904.7 v5(5242.18,4883.33) ; v1(5260.13,5551.15) 5261.22,5551.15 5265.02,5547.35 Y3.2@5329.46,5547.35 ; v1(5273.51,5044.52) C6.2@5318.01,5044.52 ; v5(5343.36,4984.51) 5343.51,4984.51 5374.43,5015.43 5374.43,5040.24 C9.2@5379.61,5045.43 ; C25.2@5366.62,4247.61 5368.43,4245.8 5408.16,4245.8 v1(5428,4225.95) ; Y3.2@5374,5547.7 v1(5406,5547.7) ; v5(5389.81,4883.33) 5415.76,4883.33 5438.04,4905.61 C12.2@5441.98,4905.61 ; v1(6279.6,3045.6) J13.4@6279.6,3145.61 ; J13.5@6279.6,3490.61 v1(6279.6,3593.4)
  Bottom Layer w22: R146.2@482,2517.26 482,2579.64 483,2580.64 ; v1(1330.6,5133.61) 1329.74,5132.75 1329.74,5092.91 1330.55,5092.1 Q3.2@1331.76,5092.1
  Bottom Layer w25: v1(734.6,4771.61) 735.68,4772.69 R98.1@801,4772.69 ; C53.2@996.6,5039.61 1003.1,5039.61 1026.97,5015.74 v1(1076.04,5015.74) 1079.6,5019.3 C55.2@1079.6,5060.98 ; Q1.2@1322.76,4113.1 1322.91,4113.1 1323.6,4113.79 1323.6,4144.3 v1(1333,4153.7) ; Q2.2@1327.16,4619.5 1327,4619.66 1327,4651.7 v1(1337,4661.7)
  Bottom Layer w30: v1(1099.47,5665.06) 1099.47,5706.12 C58.1@1120.1,5726.75
  other v1: 4967.35,54.61 2290.63,333.33 2508.93,379.28 3474,395 3162.6,413.61 4148.11,467.59 2852.71,525.68 2251,549 3715.6,562.61 3853.6,573.61 2634.65,689.24 6296,790 6237,791 6219,825 6134.6,825.61 3056.6,923.13 6244,967.6 3847.6,1113.61 3129.37,1175.9 4174.5,1178.75 3366.82,1237.18 3769,1248 805.58,1258.11 4240.88,1260.12 1740.78,1306.69 358.65,1311.96 415.14,1311.96 471.64,1311.96 528.13,1311.96 329.42,1359.07 385.91,1359.07 442.4,1359.07 498.89,1359.07 2971,1367 2208,1425 3945.35,1492.35 3624.48,1510.16 6260.6,1529.61 3512.41,1561.73 4640,1619.83 2047.81,1640.29 648,1657 3597,1657.87 598.6,1696.61 1732,1701 3423,1715.74 2131.55,1729.72 2236.89,1735.68 2081,1739 1777,1747 4016.68,1759.34 2376.08,1767.36 1668,1770 2962.17,1808.94 2443.43,1812.7 2722.19,1812.4 3061.29,1812.4 4619.94,1817.61 1860,1821 1936,1821 3237.52,1853.46 1710,1860 562,1900.55 1939,1904 2002,1905 2074,1905.95 2318.01,1906.48 2259.47,1907.61 2968.6,1914.61 2879.42,1920.49 2398.51,1921.89 2503.03,1922.01 2733.99,1924.42 3162.11,1924.42 3046.47,1926.39 6282.6,1964.61 6322.6,1964.61 3330.99,2020.57 3164.9,2026.72 563,2027.92 1917,2029 2767.4,2032.51 1803.74,2034.01 1745.19,2035.14 1990.69,2035.14 1860.21,2035.67 2105.71,2035.67 2906.93,2036.44 2256.72,2038.33 2338.82,2038.33 2420.92,2038.33 2503.03,2038.33 6280,2089 6331,2090 1710,2095 3305,2144.46 3093.31,2146.05 2997.06,2150.33 2437.41,2153.05 2747.74,2154.36 2853.87,2154.36 2516,2156 2371.43,2157.2 1919,2166 2250,2166 1983,2168 564,2199.9 3373.6,2252.61 2720.23,2262.45 3208.34,2264.06 2949.33,2266.72 3104.86,2266.72 2410.06,2297.41 2325.2,2321.41 1932,2327 2074,2327 2001,2328 566,2329 1857,2329 3345.6,2484.59 4016,2593.7 298,2637.33 354.49,2637.33 410.98,2637.33 467.48,2637.33 4087,2668.7 337.54,2682.81 394.03,2682.81 450.52,2682.81 507.01,2682.81 4274,2856.7 4362,2943.7 4453,3037.7 283.6,3492.09 440.39,3529.7 283.6,3535.61 365.6,3558.61 440.39,3581.7 4259.41,3589.28 823,3595.7 874,3595.7 927,3595.7 4337.58,3597.82 364.6,3613.61 441.39,3638.7 3937.88,3791.92 4020.93,3798.15 1131,3808.7 2512,3813.7 1132,3885.7 2510,3944.7 3763,3969.7 3872,3970.7 3972,3970.7 2510,4066.7 4071.6,4143.61 2510,4165.7 2509,4285.7 1127,4327.7 3459.92,4384.32 1127,4406.7 5000,4499.7 4950,4500.7 5052,4500.7 2396.29,4701.86 2498.29,4701.86 2591.29,4701.86 2396.29,4829.86 2498.29,4829.86 2591.29,4829.86 1116,4876.7 4811.6,4927.61 2396.29,4941.86 2498.29,4941.86 2591.29,4941.86 1115,4952.7 3678.98,4990.61 3101,5010.7 3625.6,5033.61 3625.6,5094.61 3624.6,5148.61 5195.31,5193.46 3622.6,5195.61 3678.6,5205.61 579.83,5232.18 639.83,5234.89 720.83,5250.89 557.83,5306.89 763.02,5308.13 558.91,5353.89 1236,5379.7 777.83,5386.89 1010.6,5388.61 556.5,5400.47 1155.6,5401.61 772.83,5437.89 557.83,5448.89 1219.78,5467.61 1154.06,5469.61 598.83,5476.89 730.83,5476.89 663.83,5477.89 1287.76,5482.47 1099.6,5489.21 1146,5542 1099.6,5542.21 1451,5546.7 2531,5551.7 2627,5551.7 2730,5551.7 2826,5551.7 1595,5553.7 1691,5553.7 1794,5553.7 1890,5553.7 2056,5554.7 2152,5554.7 2255,5554.7 2351,5554.7 1287.6,5571.61 1087.75,5614.56 415.6,5615.61 452.6,5615.61 485.6,5615.61 1024.6,5616.61 1223.6,5620.61 1283.6,5622.61 1450,5660.7 2530,5665.7 2626,5665.7 2729,5665.7 2825,5665.7 1594,5667.7 1690,5667.7 1793,5667.7 1889,5667.7 2055,5668.7 2151,5668.7 2254,5668.7 2350,5668.7 578.51,5696.79 1451,5776.7 2531,5781.7 2627,5781.7 2730,5781.7 2826,5781.7 5368,5781.7 1595,5783.7 1691,5783.7 1794,5783.7 1890,5783.7 2056,5784.7 2152,5784.7 2255,5784.7 2351,5784.7 5368,5826.7 5369,5872.7 415.6,5919.61 1124.6,5936.61 1210.48,5942.17 1045.6,5953.61 1124.87,6007.23 1231.6,6024.61 1035.6,6058.61 1138.6,6093.61 1264.6,6099.61
  other v2: 3724,1855.7 3774,1855.7 3824,1855.7 3874,1855.7 3924,1855.7 3724,1915.7 3774,1915.7 3824,1915.7 3874,1915.7 3924,1915.7 3724,1965.7 3774,1965.7 3824,1965.7 3874,1965.7 3924,1965.7 3724,2040.7 3774,2040.7 3824,2040.7 3874,2040.7 3924,2040.7 3674,2090.7 3724,2090.7 3774,2090.7 3824,2090.7 3874,2090.7 3924,2090.7 3874,2150.7 3924,2150.7 235,3774.7 386,3774.7 527,3775.7 238,3971.7 386,3971.7 529,3971.7 239,4154.7 386,4155.7 531,4155.7 234,4310.7 385,4310.7 526,4311.7 237,4507.7 385,4507.7 528,4507.7 238,4690.7 385,4691.7 530,4691.7 234,4858.7 382,4858.7 525,4858.7 234,5055.7 382,5055.7 525,5055.7 234,5239.7 382,5239.7 525,5239.7
  other v3: 2657.7,1801.7 2659.93,1919.7 2661.87,2034.35 2656.94,2153.7 2656.81,2271.53
  other v5: 635,3361.3 612.36,3398.7 657.64,3398.7 635,3436.1 5288.63,4836.87 5343.36,4836.87 5288.63,4883.33 5343.36,4883.33 5242.18,4938.06 5288.63,4938.06 5343.36,4938.06 5389.81,4938.06 5288.63,4984.51 5095.41,5495.43 5037.34,5553.5 5153.48,5553.5 5095.41,5611.58
GND_1: J1.1 J1.3 J1.5 J1.6 J1.7 J1.9 J1.12 J1.13 J1.15 J1.18 J1.19 J1.21 J1.23 J1.25 J1.28 J1.29 J1.31 J1.34 J1.35 J1.37 J1.38 J1.39 J1.41 J1.43 J1.45 J1.47 J1.48 J1.49 J1.51 J1.52 J1.58 J1.MP1 J1.MP2 J1.MP3 J1.MP4 J2.2 J2.4 J2.6 J2.8 J2.10 J2.12 J2.14 J2.16 J2.18 J2.20 J2.22 J2.24 J2.26 J2.28 J2.30 J2.32 J2.34 J2.36 | length 992.3
  Top Layer w10: J1.15@8469.11,1186.22 8469,1186.22 8469,1217.72 J1.13@8469.11,1217.72
  Bottom Layer w10: J1.48@8469.11,682.28 8470.11,683.29 8507.14,683.29 8513,689.15 8513,839.76 ; J1.38@8469.11,839.76 8513,839.76 ; J1.34@8469.11,902.76 8513,902.76 ; J1.28@8469.11,997.24 8509,997.24 8513,997.24 ; J1.18@8469.11,1154.72 8513,1154.72 ; J1.12@8469.11,1249.21 8513,1249.21 ; J1.6@8469.11,1343.7 8470.11,1342.7 8507.14,1342.7 8513,1336.84 8513,1249.21 ; 8513,839.76 8513,902.76 ; 8513,902.76 8513,997.24 ; 8513,997.24 8513,1154.72 ; 8513,1154.72 8513,1249.21
  other v1: 8072,-124 7894,-116 8244,-113 7742,-86 7611,-70 8076,18 7919,21 8228,26 7735,28 8329,62 7602.74,66.06 8076,119 8229,134 7606,177 8357,180 8494,195 8135,228 8242.61,236.36 8302,324 7919,378 8006.81,384.89 7922,474 8019,507 7948,567 8083,577 7937,692 8104,695 8064,782 7932,786 7944,883 8119,986 8390.02,997.06 8002.98,1114.97 8241,1117 8389.33,1146.67 8324,1197 8234,1198 8224,1266 8316,1266 7957,1299 8158,1331 8238,1341 8054,1356 8389.14,1393.97 8154.9,1422.92 8052.34,1463.12 7944.23,1490.84 8280,1526 7996,1539 8260,1626 8159,1627 8368,1709 7624,1711 8481,1712 8027,1726 8156,1727 8262,1755 7621,1804 7915,1837 8017,1842 8157,1847 8298,1854 7763,1950 7888.55,1950.48 8017,1952 8152,1952 8302,1955 7876,2047 8294,2047 7744.45,2048.06 8012,2048 8150,2054
GND_2: J19.1 J19.3 J19.5 J19.6 J19.7 J19.9 J19.12 J19.13 J19.15 J19.18 J19.19 J19.21 J19.23 J19.25 J19.28 J19.29 J19.31 J19.34 J19.35 J19.37 J19.38 J19.39 J19.41 J19.43 J19.45 J19.47 J19.48 J19.49 J19.51 J19.52 J19.58 J19.MP1 J19.MP2 J19.MP3 J19.MP4 J22.1 J22.3 J22.5 J22.6 J22.7 J22.9 J22.12 J22.13 J22.15 J22.18 J22.19 J22.21 J22.23 J22.25 J22.28 J22.29 J22.31 J22.34 J22.35 J22.37 J22.38 J22.39 J22.41 J22.43 J22.45 J22.47 J22.48 J22.49 J22.51 J22.52 J22.58 J22.MP1 J22.MP2 J22.MP3 J22.MP4 | length 76.8
  Top Layer w20: J22.5@6550.68,555.91 6624.82,555.91 6625.92,557 v1(6627,557)
  other v1: 7028.81,-149.85 7129.41,-150.46 6928.2,-149.23 6827.6,-148.62 6518.91,-144.09 6718.91,-144.09 6618.3,-143.48 7028.81,-49.85 7129.41,-50.46 6928.2,-49.23 6827.6,-48.62 6518.91,-44.09 6718.91,-44.09 6618.3,-43.48 7230.01,48.92 7028.81,50.15 7129.41,49.54 6928.2,50.77 6827.6,51.38 6718.91,55.91 7230.01,148.92 7028.81,150.15 7129.41,149.54 6928.2,150.77 6827.6,151.38 6718.91,155.91 7230.01,248.92 7028.81,250.15 7129.41,249.54 6928.2,250.77 6827.6,251.38 6718.91,255.91 7230.01,348.92 7028.81,350.15 7129.41,349.54 6928.2,350.77 6827.6,351.38 6718.91,355.91 7230.01,448.92 7028.81,450.15 7129.41,449.54 6928.2,450.77 6827.6,451.38 6718.91,455.91 7230.01,548.92 7028.81,550.15 7129.41,549.54 6928.2,550.77 6827.6,551.38 6718.91,555.91 7302,614 6630,650.39 7307,678 6635,741 7299,840 7302,902 6627,902.36 7317,997 6625,998 6625,1060 7295,1163 6627,1219 7264,1241 6727.67,1285.44 6631.7,1287.49 7214.01,1331.92 7314.61,1331.31 7012.81,1333.15 7113.41,1332.54 6912.2,1333.77 6811.6,1334.38 6727.67,1385.44 6631.7,1387.49 7312.22,1426.68 7214.01,1431.92 7012.81,1433.15 7113.41,1432.54 6912.2,1433.77 6811.6,1434.38 6727.67,1485.44 6631.7,1487.49 7214.01,1531.92 7012.81,1533.15 7113.41,1532.54 6912.2,1533.77 6811.6,1534.38 6727.67,1585.44 6631.7,1587.49 7214.01,1631.92 7314.61,1631.31 7012.81,1633.15 7113.41,1632.54 6912.2,1633.77 6811.6,1634.38 6727.67,1685.44 6631.7,1687.49 7304,1719 7214.01,1731.92 7012.81,1733.15 7113.41,1732.54 6912.2,1733.77 6811.6,1734.38 6727.67,1785.44 7214.01,1831.92 7012.81,1833.15 7113.41,1832.54 6912.2,1833.77 6811.6,1834.38 6727.67,1885.44 6524.02,1886.54 6631.7,1887.49 7214.01,1931.92 7012.81,1933.15 7113.41,1932.54 6912.2,1933.77 6811.6,1934.38 7214.01,2031.92 7012.81,2033.15 7113.41,2032.54 6912.2,2033.77 6811.6,2034.38
GTX_CLK: R20.1 U5.39 | length 2371.9
  Top Layer w8: U5.39@4051.41,1973.7 4165.99,1973.7 cw(c4165.99,1944.14) 4186.9,1965.04 4262.84,1889.1 ccw(c4333.55,1959.81) 4333.55,1859.81 4635.6,1859.81 cw(c4635.6,1759.81) 4706.32,1830.52 5193.64,1343.2 cw(c5122.92,1272.49) 5222.92,1272.49 5222.92,1015.42 ccw(c5322.92,1015.42) 5322.92,915.42 5735.34,915.42 ccw(c5735.34,1008.75) R20.1@5801.34,942.76
GTX_CLK_1: J1.36 J2.29 | length 1014.5
  Bottom Layer w10: J2.29@7833.6,1534.61 8023.6,1344.61 8023.6,1166.61 8318.94,871.26 J1.36@8469.11,871.26
GTX_CLK_2: J22.36 R202.1 | length 527.8
  Bottom Layer w10: J22.36@6550.68,1028.35 6551.29,1027.73 6772.47,1027.73 6823.78,976.42 R202.1@7056.98,976.42
GTX_CLK_LP: J19.36 R201.2 | length 287.8
  Bottom Layer w10: R201.2@7104.22,879.33 7111.03,872.52 7119.48,872.52 7120.83,871.17 J19.36@7388.6,871.17
HUB_D1_N: R180.2 R184.1 R187.2 | length 1498.5
  Top Layer w5: R180.2@4648,4819.32 4682.82,4784.5 ccw(c4692,4793.68) v1(4692,4780.7) ; R187.2@4792.62,5598.72 cw(c4792.62,5590.85) 4798.18,5596.42 4803.3,5591.3 cw(c4798.71,5586.72) 4805.19,5586.72 ccw(c4810.35,5586.72) 4806.7,5583.07 ccw(c4810.35,5586.72) 4810.35,5581.56 4812.39,5581.56 ccw(c4812.39,5591.65) 4819.53,5584.52 ; v4(4828,5592) ccw(c4840.59,5592) 4840.59,5579.41 4854.92,5579.41 ccw(c4854.92,5584.41) 4858.46,5580.87 ccw(c4854.92,5584.41) 4859.92,5584.41 4859.92,5584.82 cw(c4865.91,5584.82) 4861.68,5589.05 4867.04,5594.41 cw(c4872.35,5589.08) R184.1@4872.35,5596.61
  Bottom Layer w5: v1(4692,4780.7) ccw(c4720.23,4780.7) 4720.23,4752.47 4817.68,4752.47 ccw(c4817.68,4795) 4860.21,4795 4860.21,5098.85 ccw(c4760.21,5098.85) 4850.81,5141.18 ccw(c4760.21,5098.85) 4830.92,5169.56 4594.27,5406.21 cw(c4671.7,5483.64) 4562.2,5483.64 4562.2,5488.36 cw(c4667.02,5488.36) 4562.2,5488.5 cw(c4667.02,5488.36) 4592.8,5562.38 4594.38,5563.95 cw(c4636.89,5521.44) 4636.89,5581.56 4802.8,5581.56 ccw(c4802.8,5614.8) 4826.31,5591.3 cw(c4828,5589.61) v4(4828,5592)
HUB_D1_P: R183.2 R185.1 R186.2 | length 1464.2
  Top Layer w5: R183.2@4705,4676.08 4706.4,4677.48 v1(4748.6,4677.48) ; R186.2@4792.62,5557.5 ccw(c4792.62,5567.01) 4799.34,5560.29 4805.09,5566.03 ccw(c4803.19,5567.92) 4805.87,5567.92 cw(c4808.55,5567.92) 4806.66,5569.82 4807.34,5570.5 cw(c4810.87,5566.96) 4810.87,5571.96 4812.69,5571.96 cw(c4812.69,5562.57) 4819.33,5569.21 ; v4@4826.31,5562.24 cw(c4833.88,5562.24) 4833.88,5569.81 4855.2,5569.81 cw(c4855.2,5564.59) 4858.89,5568.28 cw(c4855.2,5564.59) 4860.42,5564.59 4860.42,5564.33 ccw(c4866.25,5564.33) 4862.13,5560.21 4867.43,5554.9 ccw(c4872.98,5560.45) R185.1@4872.98,5552.61
  Bottom Layer w5: v1(4748.6,4677.48) 4748.6,4722.47 cw(c4769,4722.47) 4769,4742.87 4819.1,4742.87 ccw(c4819.1,4793.58) 4869.81,4793.58 4869.81,5098.89 ccw(c4760.31,5098.89) 4837.74,5176.32 4601.09,5412.97 cw(c4671.8,5483.68) 4571.8,5483.68 4571.8,5486.38 cw(c4671.8,5486.38) 4601.09,5557.09 cw(c4637,5521.18) 4637,5571.96 4802.82,5571.96 cw(c4802.82,5538.75) 4826.31,5562.24 ccw(c4828.01,5563.94) v4(4828.01,5561.53)
HUB_D2_N: R192.1 R195.2 R196.2 | length 140.2
  Top Layer w5: R196.2@4792.62,5509.5 cw(c4792.62,5500.25) 4799.17,5506.79 4804.27,5501.69 cw(c4800.65,5498.07) 4805.77,5498.07 ccw(c4810.89,5498.07) 4807.27,5494.45 4807.37,5494.35 ccw(c4811.24,5498.21) 4811.24,5492.74 4813.1,5492.74 ccw(c4813.1,5502.72) 4820.15,5495.66 ; v4(4828,5504) cw(c4828,5492.89) 4835.85,5500.75 4838.83,5497.77 ccw(c4848.41,5507.35) 4848.41,5493.8 4854.2,5493.8 ccw(c4854.2,5499.63) 4858.32,5495.51 ccw(c4855.36,5498.46) 4859.54,5498.46 cw(c4863.72,5498.46) 4860.76,5501.42 4866.07,5506.72 cw(c4872.79,5500) R192.1@4872.79,5509.5
  Bottom Layer w5: R195.2@4792.62,5509.5 cw(c4792.62,5500.25) 4799.17,5506.79 4804.27,5501.69 cw(c4800.65,5498.07) 4805.77,5498.07 ccw(c4810.89,5498.07) 4807.27,5494.45 ccw(c4811.38,5498.56) 4810.46,5492.82 ccw(c4811.38,5498.56) 4811.06,5492.75 ccw(c4811.38,5498.56) 4811.38,5492.74 ccw(c4811.38,5506.88) 4821.37,5496.88 4828,5503.51 v4(4828,5504)
HUB_D2_P: R193.1 R194.2 R199.2 | length 146.6
  Top Layer w5: R199.2@4792.62,5468.5 ccw(c4792.62,5478.01) 4799.34,5471.29 4805.03,5476.97 ccw(c4802.97,5479.02) 4805.87,5479.02 cw(c4808.77,5479.02) 4806.72,5481.06 4807.34,5481.69 cw(c4810.87,5478.14) 4810.87,5483.14 4813.69,5483.14 cw(c4813.69,5471.35) v4@4822.03,5479.69 ; v4(4830,5474) ccw(c4830,5485.11) 4837.85,5477.25 4842.27,5481.66 cw(c4848.41,5475.5) 4848.41,5484.2 4854.2,5484.2 cw(c4854.2,5478.38) 4858.32,5482.5 cw(c4855.36,5479.55) 4859.54,5479.55 ccw(c4863.72,5479.55) 4860.76,5476.6 4866.07,5471.29 ccw(c4872.79,5478.01) R193.1@4872.79,5468.5
  Bottom Layer w5: R194.2@4805.02,5476.97 R194.2@4799.34,5471.29 ; R194.2@4805.87,5478.48 cw(c4804.26,5478.48) 4805.87,5478.41 cw(c4804.26,5478.48) 4805.4,5477.34 4805.03,5476.97 ccw(c4802.97,5479.02) 4805.87,5479.02 cw(c4808.77,5479.02) 4806.72,5481.06 cw(c4811.74,5476.04) 4810.41,5483.02 cw(c4811.74,5476.04) 4811.29,5483.13 cw(c4811.74,5476.04) 4811.74,5483.14 4812.1,5483.14 cw(c4812.1,5467.53) 4823.14,5478.57 4826.1,5475.62 ccw(c4830,5479.51) v4(4830,5474) ; R194.2@4799.34,5471.29 cw(c4792.62,5478.01) 4794.86,5468.77 cw(c4792.62,5478.01) R194.2@4792.62,5468.5 ccw(c4792.62,5478.01) R194.2@4799.34,5471.29
INT_ECC_N: J8.6 R43.1 U5.56 | length 3387.2
  Top Layer w8: J8.6@3289.6,4966.61 3261.94,4966.61 ccw(c3261.94,4889.26) 3207.25,4943.95 3061.29,4797.99 ccw(c3132,4727.28) 3032,4727.28 3032,3747.45 ccw(c3132,3747.45) 3061.29,3676.74 3516.31,3221.72 cw(c3445.6,3151.01) 3545.6,3151.01 3545.6,2801.09 ccw(c3645.6,2801.09) 3574.89,2730.38 3796.63,2508.64 cw(c3750.47,2462.48) 3796.67,2508.6 cw(c3750.47,2462.48) 3815.75,2462.48 3815.75,2382.7 3814.73,2349.52 cw(c3775,2350.7) 3814.62,2347.53 cw(c3775,2350.7) 3814.58,2347.09 3814.38,2344.86 3813.73,2337.64 3812.88,2328.21 3811.36,2311.36 ccw(c3825.13,2310.12) 3811.31,2310.59 U5.56@3809.4,2255.08
  Top Layer w10: J8.6@3289.6,4966.61 3340.6,4915.61 R43.1@3500.98,4915.61
INT_PWDN: J8.12 J15.2 R46.1 R55.1 U5.60 | length 2869.9
  Top Layer w8: v3(3675.6,2490.61) 3675.6,2448.57 ccw(c3763.63,2448.57) 3701.35,2386.35 ; 3701.38,2386.32 3721.16,2366.54 ; 3721.18,2366.52 cw(c3698.23,2343.61) 3730.66,2343.61 U5.60@3730.66,2255.08
  Top Layer w10: J8.12@3289.6,4666.61 3334.6,4621.61 R46.1@3500.98,4621.61
  SIG1 w10: J8.12@3289.6,4666.61 3582.16,4374.05 cw(c3511.45,4303.34) 3611.45,4303.34 v1(3611.45,4271.61) 3611.45,3906.94 cw(c3547.89,3906.94) J15.2@3592.83,3862 cw(c3552.35,3821.52) 3609.6,3821.52 3609.6,2756.03 ccw(c3709.6,2756.03) 3638.89,2685.32 3646.31,2677.9 cw(c3575.6,2607.18) 3675.6,2607.18 v3(3675.6,2490.61)
  Bottom Layer w10: v1(3611.45,4271.61) R55.1@3611.45,4325.14
INT_STTMCHNE_N: J8.8 R44.1 U5.55 | length 3250.3
  Top Layer w8: J8.8@3289.6,4866.61 3246.11,4866.61 ccw(c3246.11,4766.61) 3175.4,4837.32 3138.29,4800.2 ccw(c3209,4729.49) 3109,4729.49 3109,3776.42 ccw(c3209,3776.42) 3138.29,3705.71 3802.33,3041.67 cw(c3731.62,2970.96) 3831.62,2970.96 3831.62,2337.64 3831.27,2326.2 U5.55@3829.09,2255.08
  Top Layer w10: J8.8@3289.6,4866.61 3339.6,4816.61 R44.1@3500.98,4816.61
INT_SUP_CUR_N: J8.4 R42.1 U5.57 | length 3529.4
  Top Layer w8: J8.4@3289.6,5066.61 ccw(c3289.6,5002.17) 3244.03,5047.73 2976.29,4779.99 ccw(c3047,4709.28) 2947,4709.28 2947,3689.9 ccw(c3047,3689.9) 2976.29,3619.18 3430.15,3165.33 cw(c3359.44,3094.62) 3459.44,3094.62 3459.44,2847.95 ccw(c3559.44,2847.95) 3488.73,2777.24 3768.79,2497.17 cw(c3698.08,2426.46) 3798.08,2426.46 ccw(c3806.08,2426.46) 3798.08,2426.38 3798.87,2351.01 cw(c3775,2350.7) 3798.82,2349.15 cw(c3775,2350.7) 3798.08,2344.61 3794.43,2330.71 ccw(c3809.4,2326.78) 3794.06,2328.88 3791.75,2311.99 ccw(c3805.44,2310.12) 3791.63,2310.59 U5.57@3789.72,2255.08
  Top Layer w10: J8.4@3289.6,5066.61 3337.6,5018.61 R42.1@3500.98,5018.61
JTAG_CLK: P1.4 R91.2 U5.28 | length 4057.5
  Top Layer w8: U5.28@3868.46,1751.38 3868.46,1666.54 4188.08,1346.92 cw(c4148.2,1307.04) 4204.6,1307.04 4204.6,1283.68 4204.6,1274.6 ccw(c4304.6,1274.6) 4233.89,1203.89 4355.67,1082.1 cw(c4334.85,1061.28) v1(4364.3,1061.28)
  SIG1 w8: P1.4@1418.49,834.31 1467.9,784.9 ccw(c1538.61,855.61) 1538.61,755.61 3617.18,755.61 ccw(c3617.18,855.61) 3687.89,784.9 3934.98,1031.99 cw(c4005.69,961.28) 4005.69,1061.28 v1(4364.3,1061.28)
  Bottom Layer w20: R91.2@1418.49,756.44 P1.4@1418.49,834.31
